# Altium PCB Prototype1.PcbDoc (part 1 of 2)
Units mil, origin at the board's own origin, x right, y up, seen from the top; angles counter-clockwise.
Board outline 2500.51 x 3790.51 mil, 6 copper layers (Signal 1, DGND, +3.3, AGND, +5/+1.2, Signal 4); 76 components, 99 nets, 527 pads, 166 vias.
Unrouted connection lines stored in the file: 15.
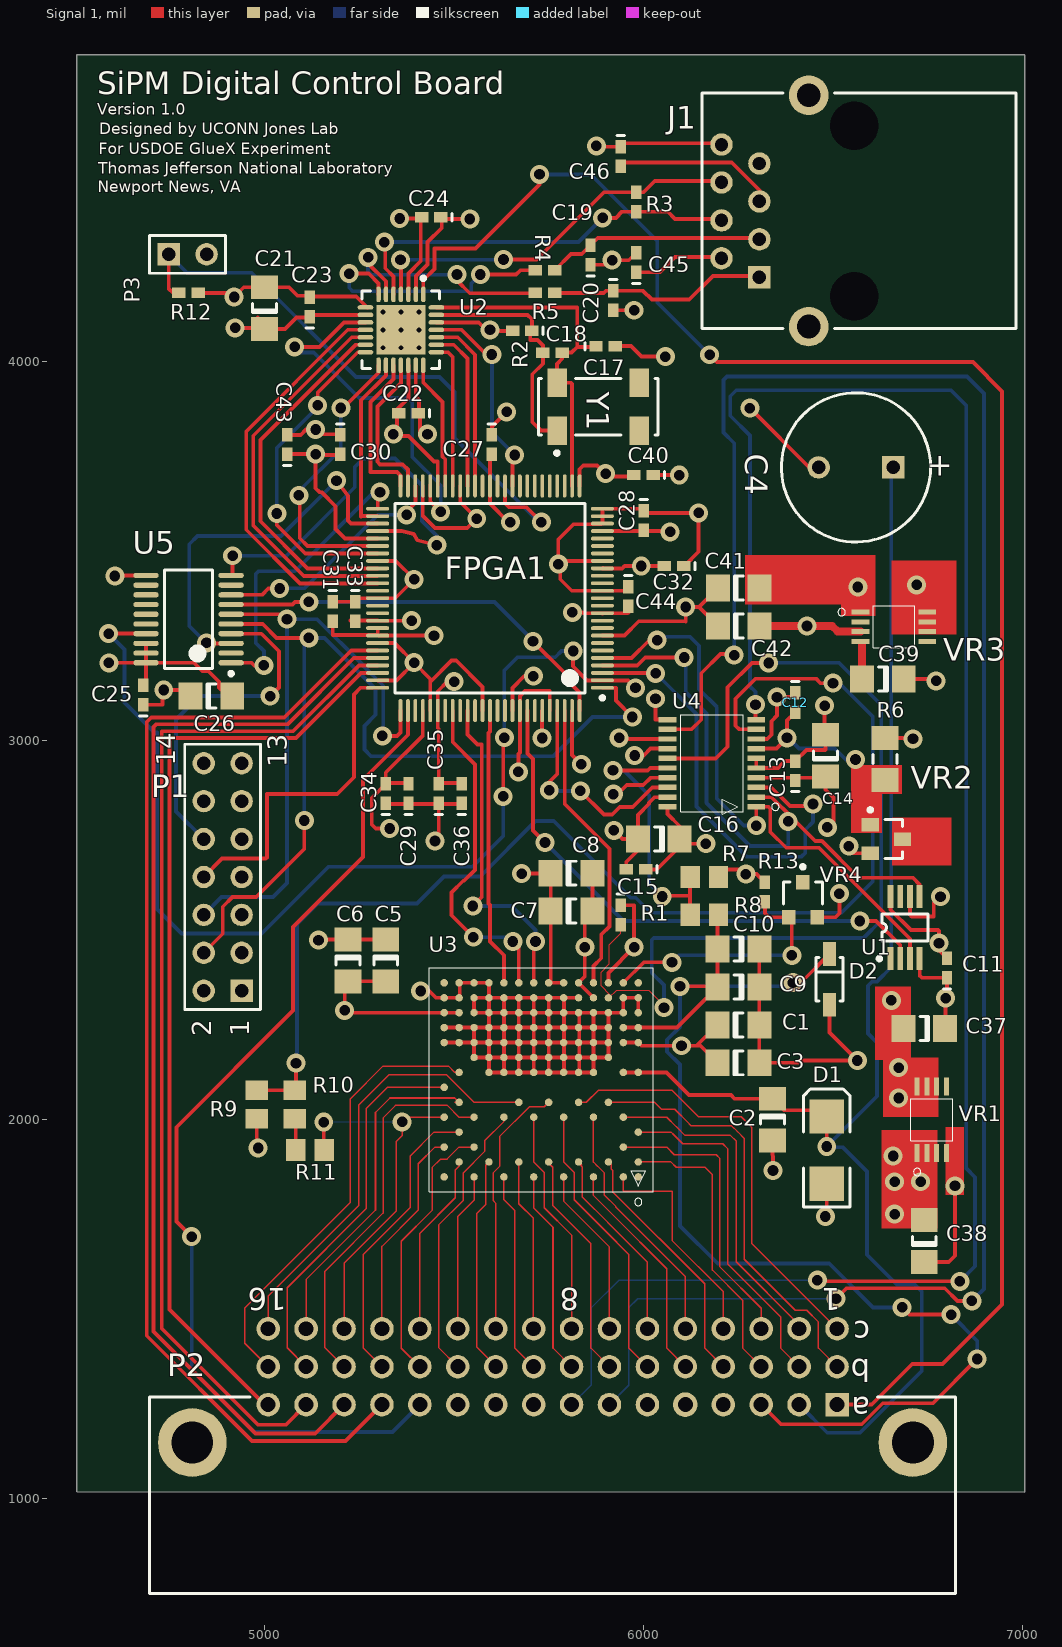
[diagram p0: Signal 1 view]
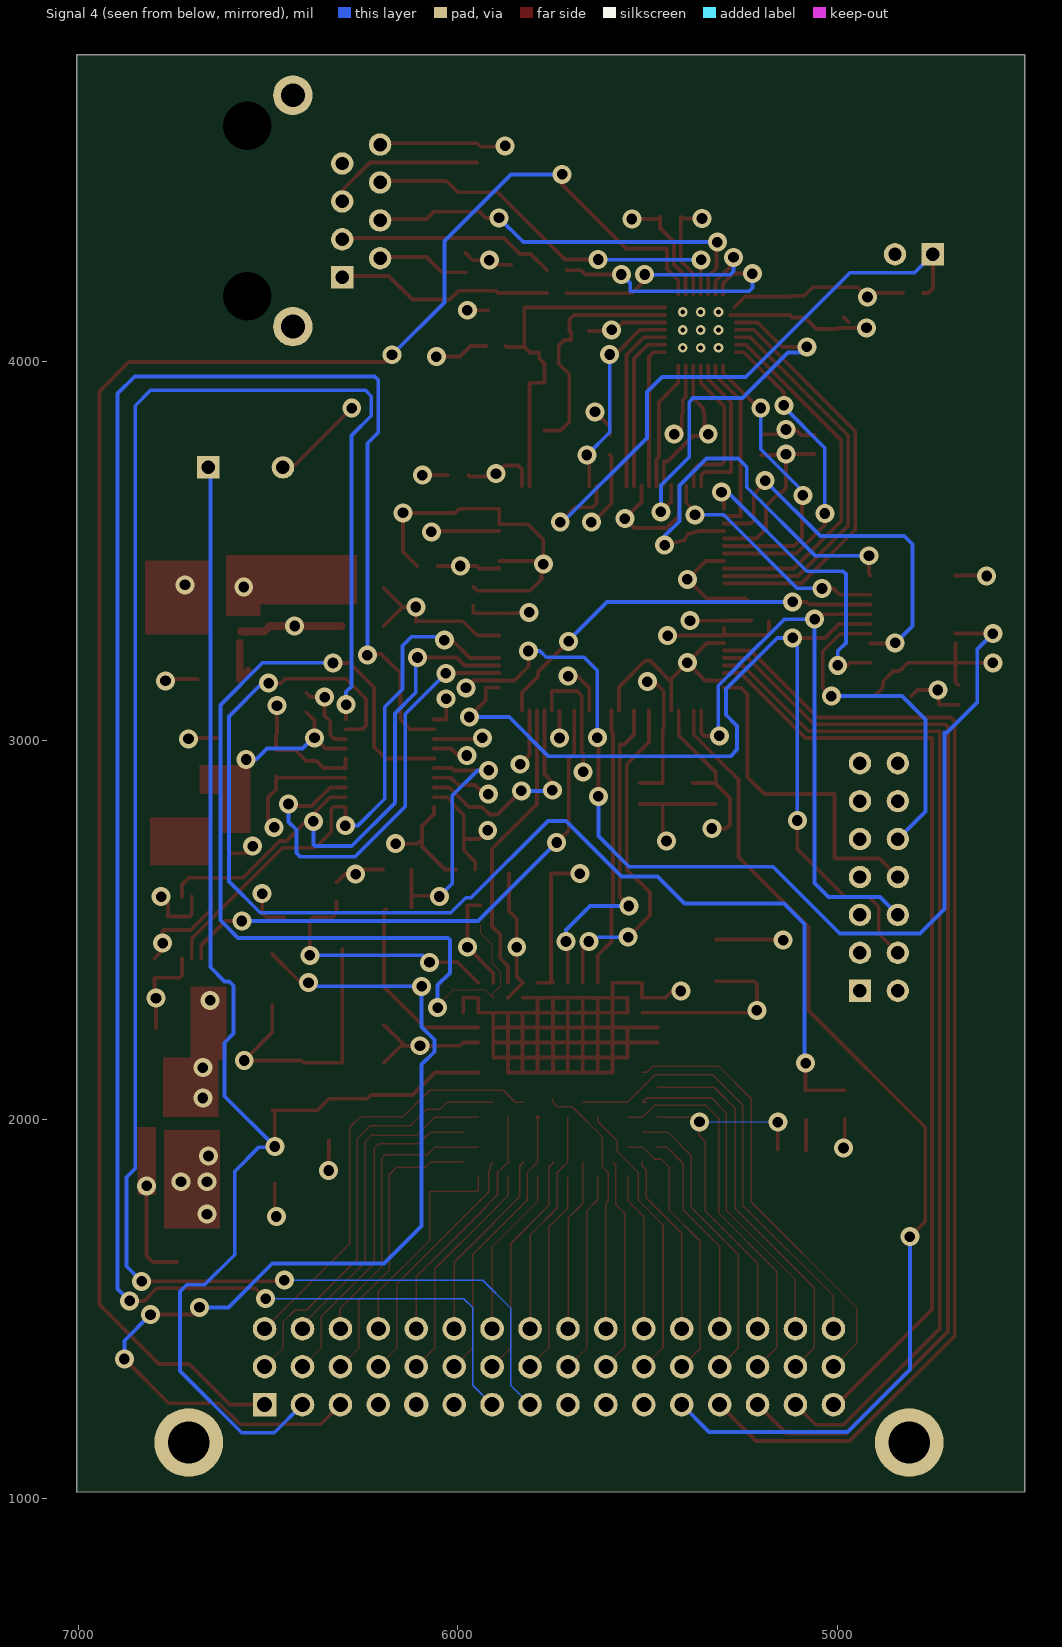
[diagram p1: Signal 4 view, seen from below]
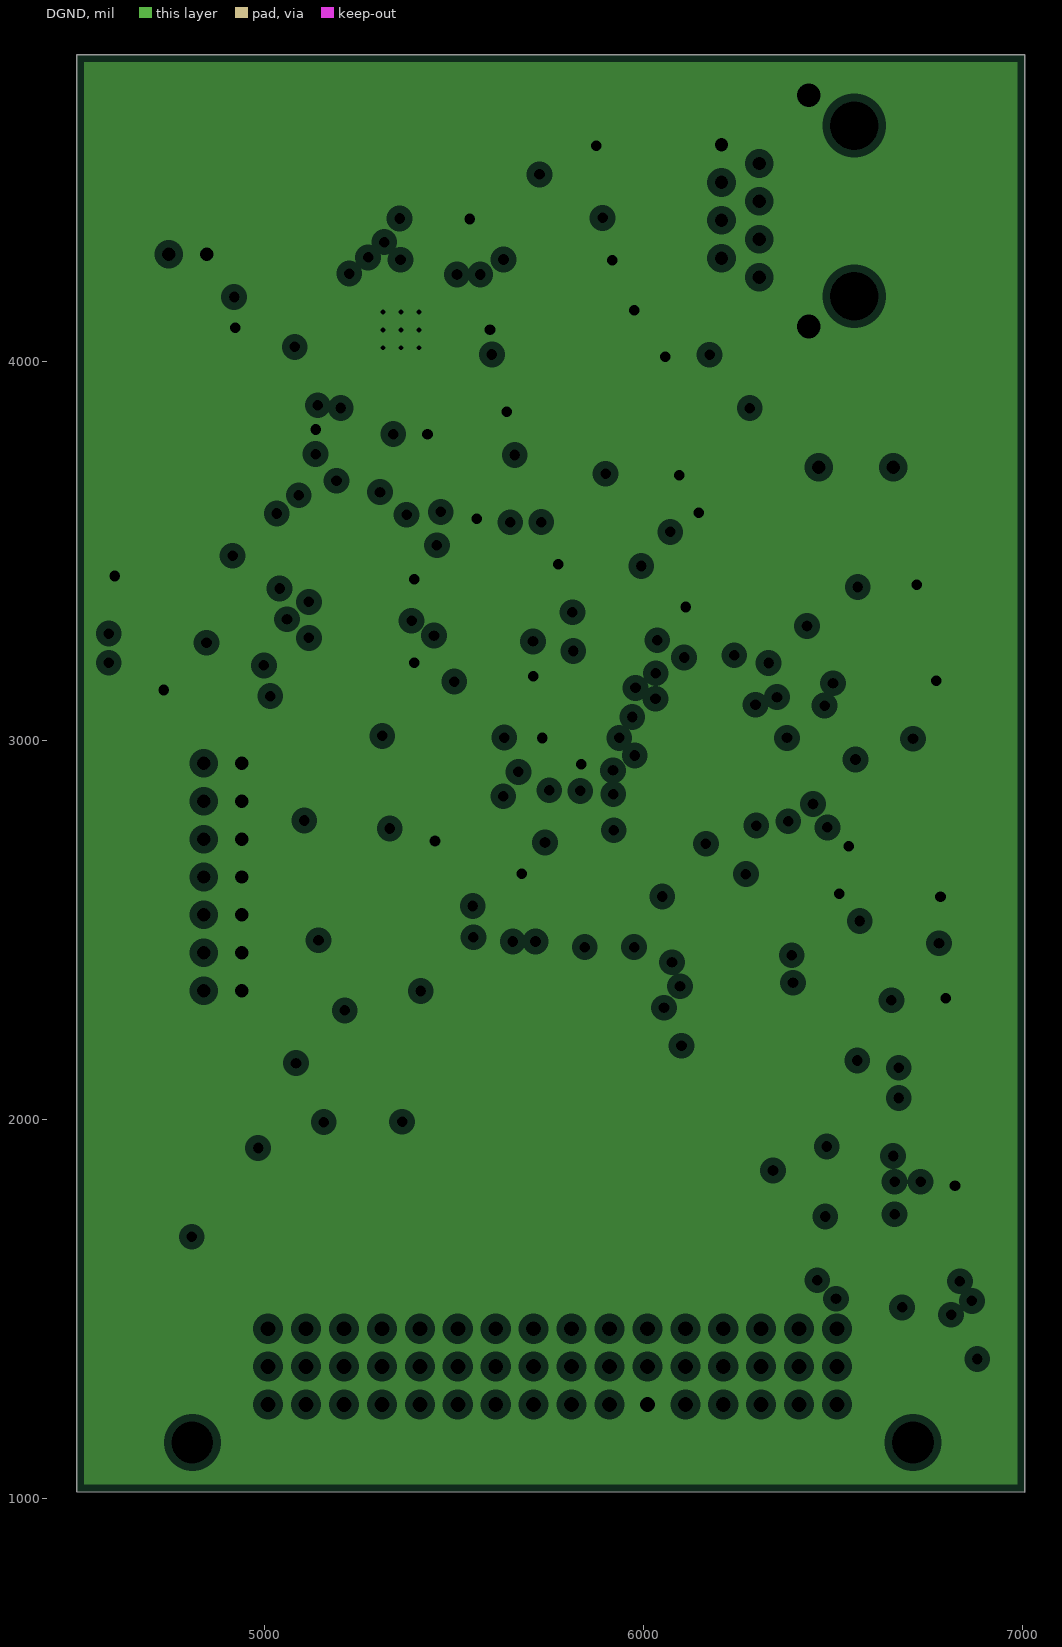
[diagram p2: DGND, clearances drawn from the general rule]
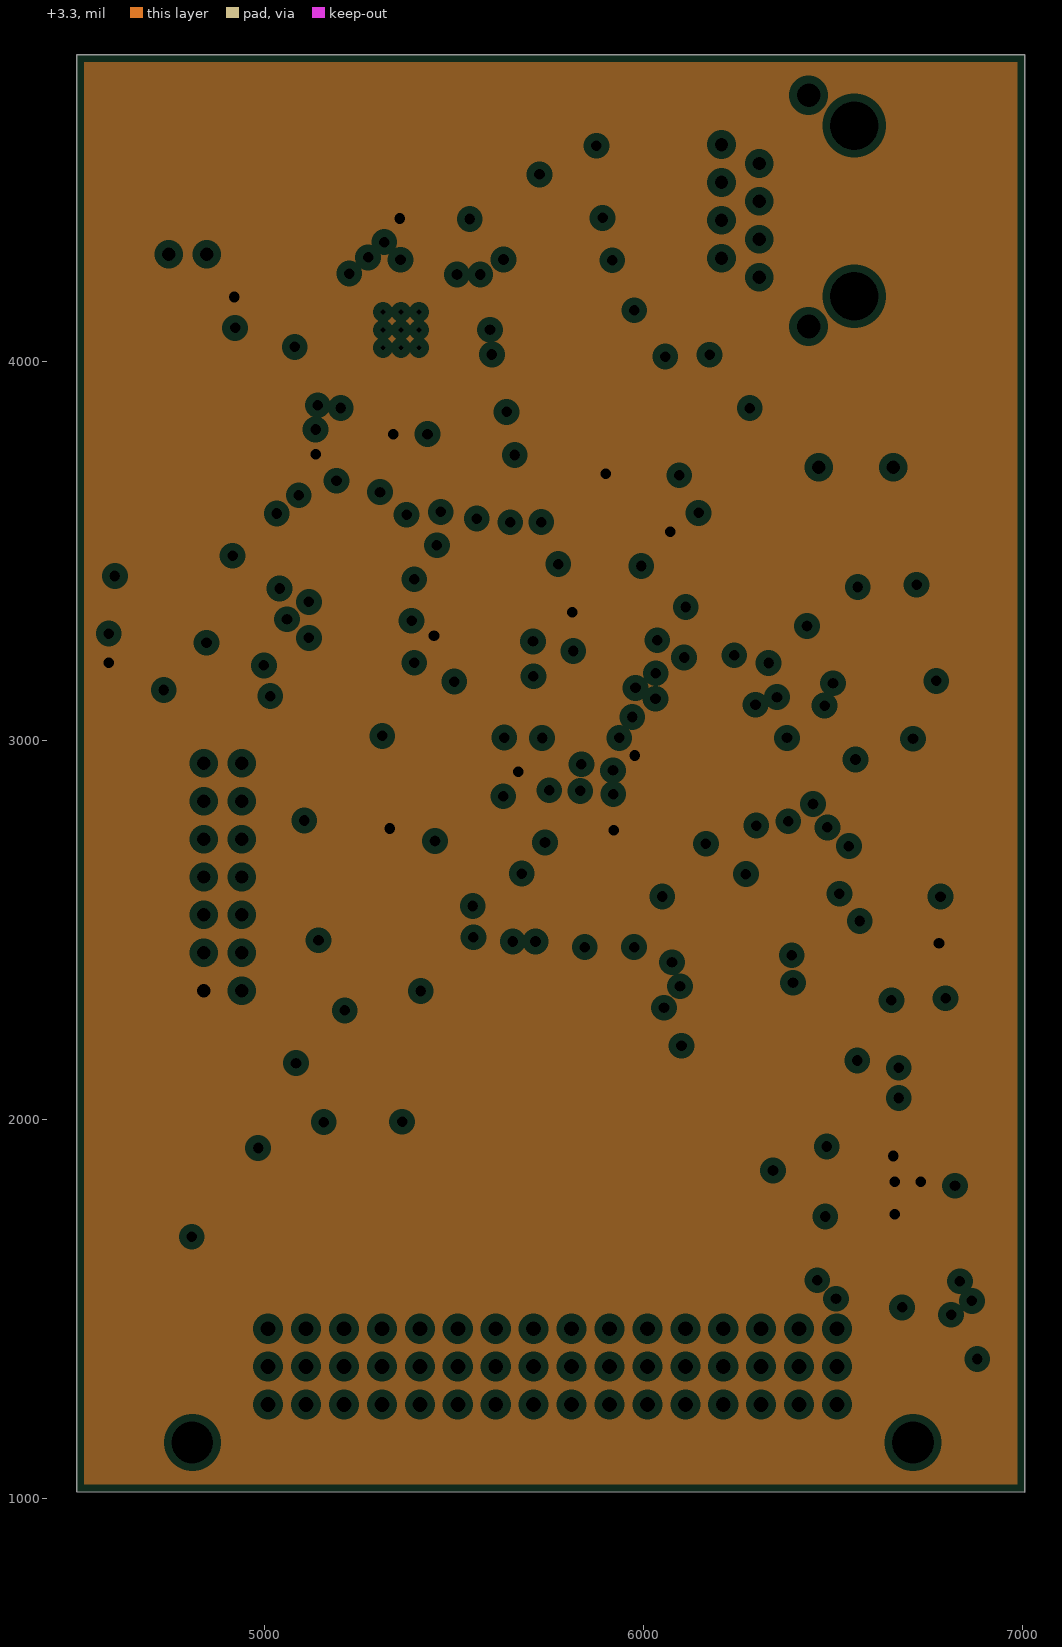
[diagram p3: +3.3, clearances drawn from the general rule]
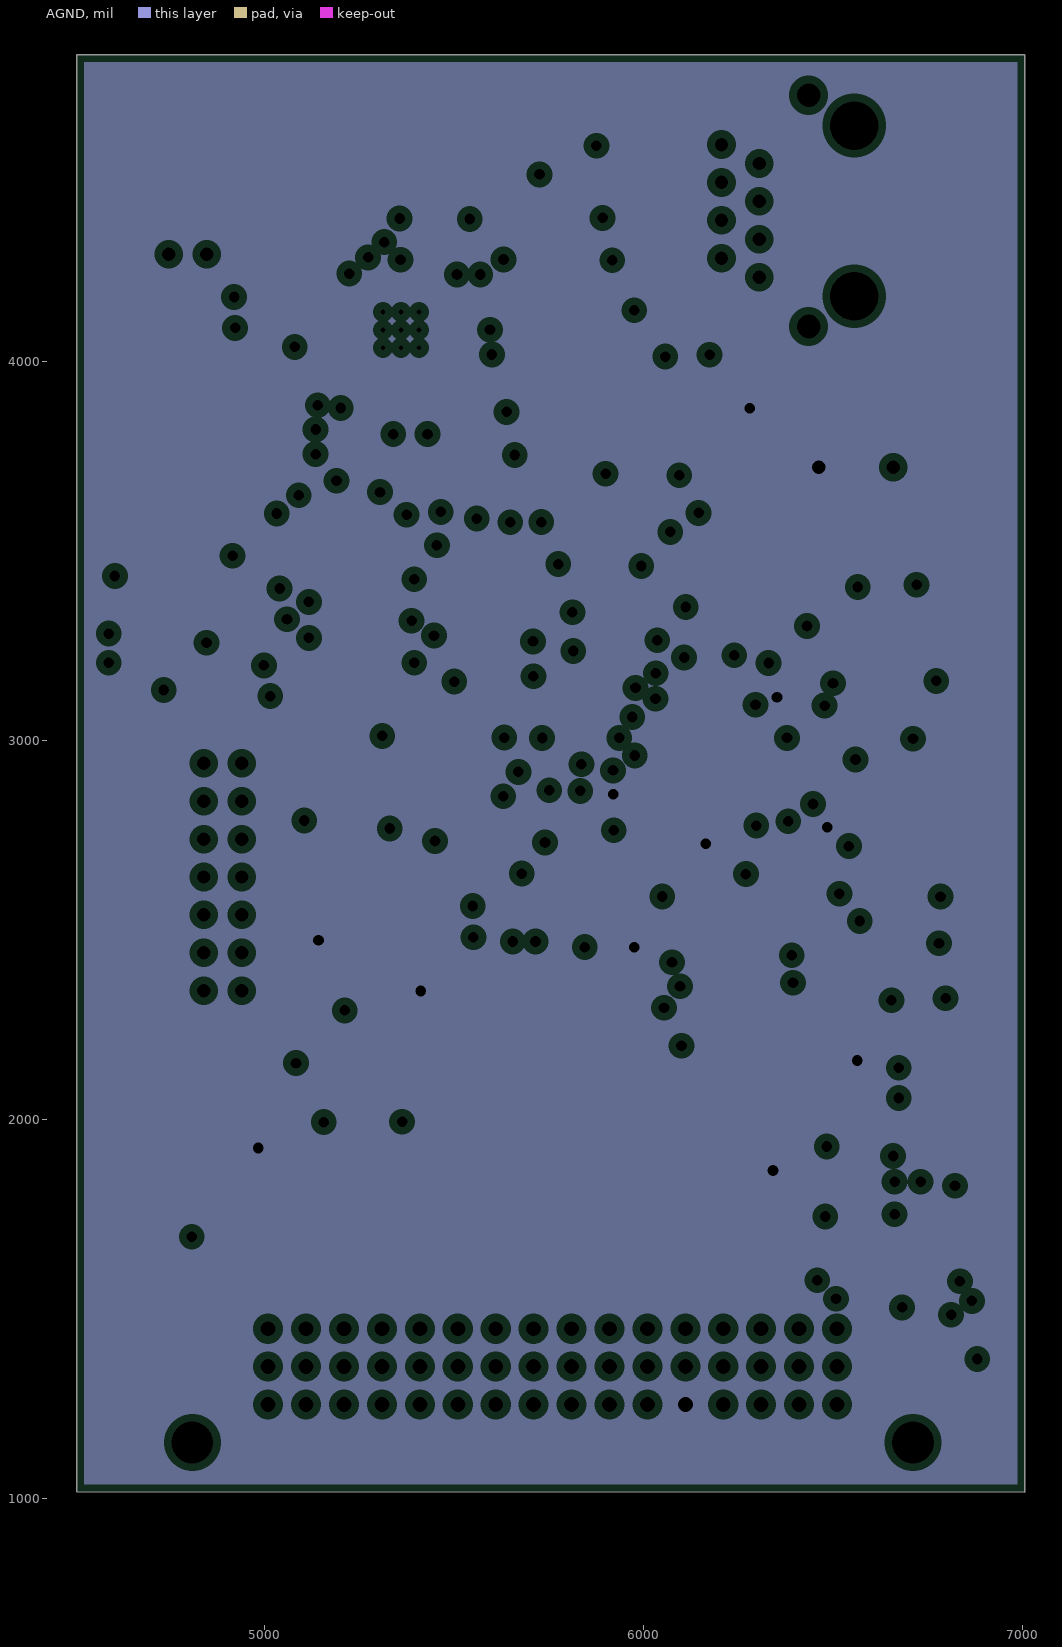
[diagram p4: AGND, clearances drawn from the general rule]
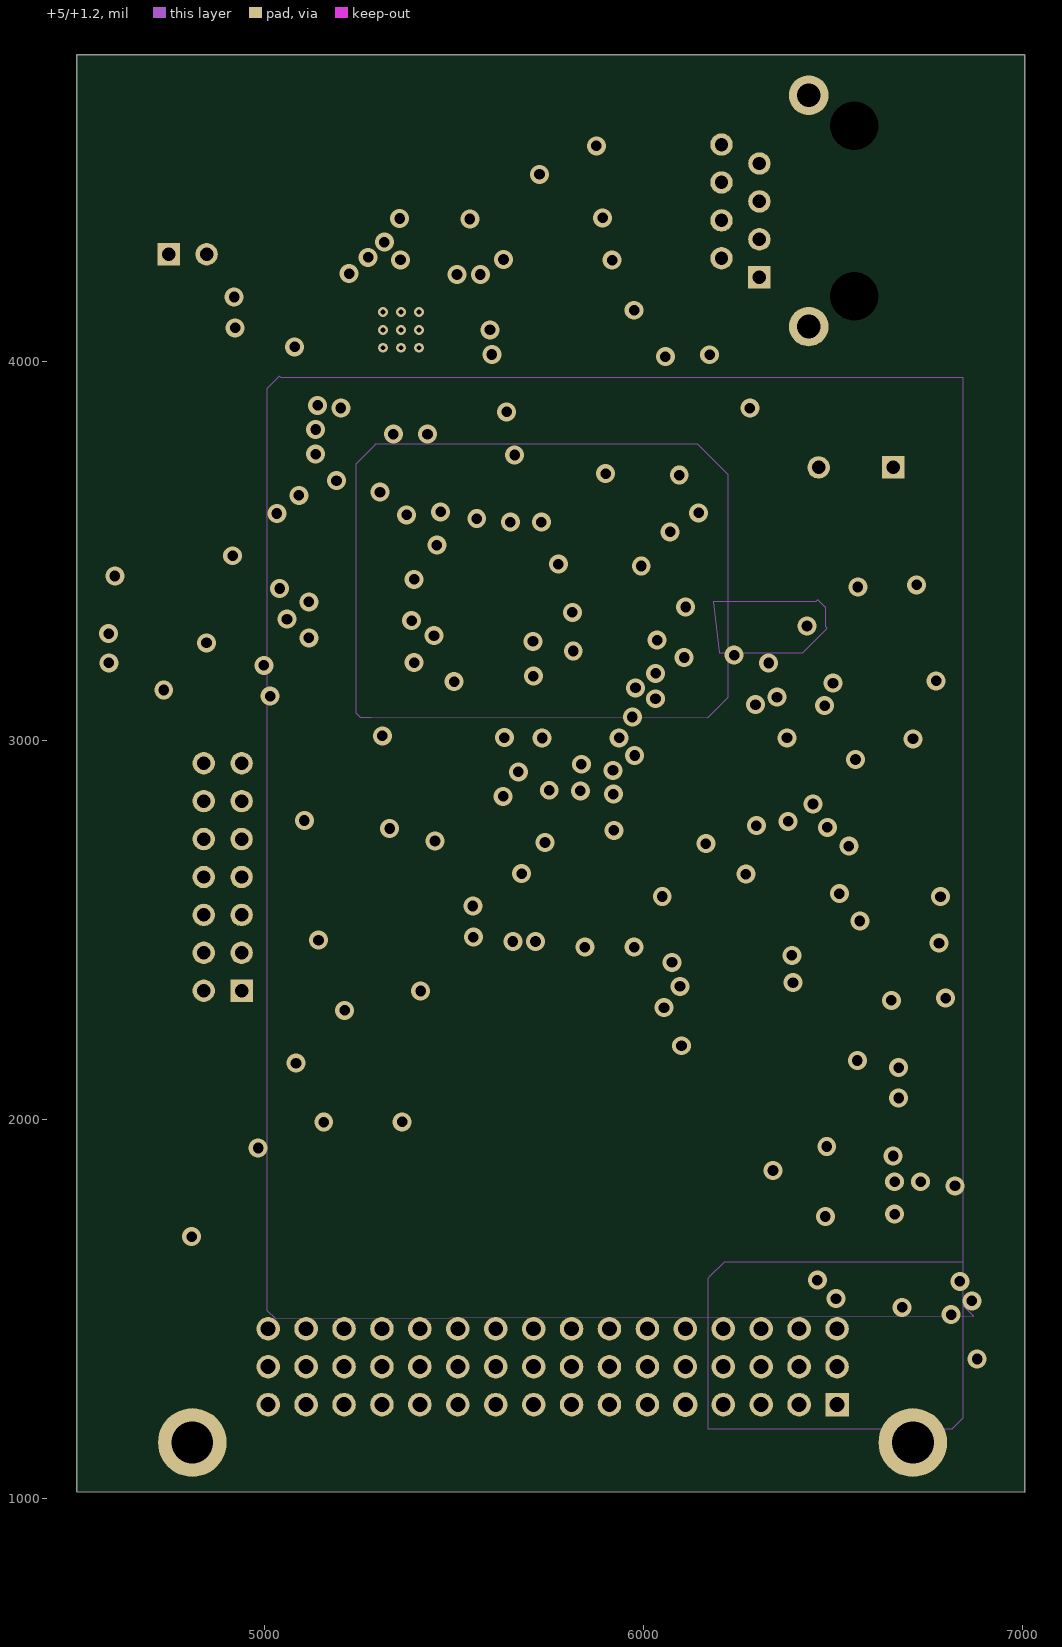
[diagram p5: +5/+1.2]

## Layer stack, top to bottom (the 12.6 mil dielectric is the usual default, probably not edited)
Signal 1: signal copper 1.4
Dielectric: core 12.6, FR-4, Dk 4.8
DGND: plane copper 1.4, net AD5535/DGND
Dielectric: prepreg 12.6, FR-4, Dk 4.8
+3.3: plane copper 1.4, net +3.3V
Dielectric: core 12.6, FR-4, Dk 4.8
AGND: plane copper 1.4, net AD5535/AGND
Dielectric: prepreg 12.6, FR-4, Dk 4.8
+5/+1.2: signal copper 1.4
Dielectric: core 12.6, FR-4, Dk 4.8
Signal 4: signal copper 1.4

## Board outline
7005.5,1017.89 7005.5,4808.4 4504.99,4808.4 4504.99,1018.96

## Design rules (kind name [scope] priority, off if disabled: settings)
Clearance "SiPM AD5535 Clearance" [(InNetClass('SiPM Bias Voltages')) vs (InComponent('U3'))] p1: gap=15.94
Clearance "CP2201 Clearance" [(InComponent('U2'))] p2: gap=4
Clearance "SiPM Bias Clearance" [InNetClass('SiPM Bias Voltages')] p3: gap=15.75
Clearance [All] p4: gap=8
ComponentClearance [All] p1: gap=10 collisioncheckmode=3 verticalgap=10
HoleSize [All] p1: absolutevalues=TRUE maxlimit=200 minlimit=1 maxpercent=80.000 minpercent=20.000
PlaneClearance [All] p1: clearance=20
PlaneConnect [All] p1: planeconnectstyle=Relief reliefexpansion=20 reliefentries=4 reliefconductorwidth=10 reliefairgap=10
PolygonConnect [All] p1: connectstyle=Relief reliefconductorwidth=10 reliefentries=4 polygonreliefangle="90 Angle"
RoomDefinition "AD5535 Power Regulators" [InComponentClass('AD5535 Power Regulators')] p1: confinementstyle=ConfineIn formatcopy=TRUE lockcomponents=FALSE outline 4775,1345 6870,1345 6870,3997.8 4775,3997.8
RoomDefinition FPGA [InComponentClass('FPGA')] p2: confinementstyle=ConfineIn formatcopy=TRUE lockcomponents=FALSE outline 4576.58,2735 6855,2735 6855,4403.79 4576.58,4403.79
RoomDefinition "Backplane Connector" [InComponentClass('Backplane Connector')] p3: confinementstyle=ConfineIn formatcopy=TRUE lockcomponents=FALSE outline 4634.69,710.9 6981.5,710.9 6981.5,1598.6 4634.69,1598.6
RoomDefinition AD5535 [InComponentClass('AD5535')] p4: confinementstyle=ConfineIn formatcopy=TRUE lockcomponents=FALSE outline 6633.36,2854.7 5410,2854.7 5410,1450 6633.36,1450
RoomDefinition AD7314 [InComponentClass('AD7314')] p5: confinementstyle=ConfineIn formatcopy=TRUE lockcomponents=FALSE outline 6594.5,2316.5 6965.5,2316.5 6965.5,2706.5 6594.5,2706.5
RoomDefinition AD7928 [InComponentClass('AD7928')] p6: confinementstyle=ConfineIn formatcopy=TRUE lockcomponents=FALSE outline 4825.67,1775.82 7046.7,1775.82 7046.7,3244.9 4825.67,3244.9
RoomDefinition CP2201 [InComponentClass('CP2201')] p7: confinementstyle=ConfineIn formatcopy=TRUE lockcomponents=FALSE outline 4520.07,3240 6992.4,3240 6992.4,4977.8 4520.07,4977.8
RoomDefinition EEPROM [InComponentClass('EEPROM')] p8: confinementstyle=ConfineIn formatcopy=TRUE lockcomponents=FALSE outline 4520.07,2135.7 5121.9,2135.7 5121.9,4105 4520.07,4105
RoomDefinition "Power and Voltage Regulators" [InComponentClass('Power and Voltage Regulators')] p9: confinementstyle=ConfineIn formatcopy=TRUE lockcomponents=FALSE outline 6519.3,1420.7 6979.7,1420.7 6979.7,2357.2 6519.3,2357.2
RoutingVias [All] p1: holewidth=28 width=50 viastyle="Through Hole" minholewidth=28 minwidth=50 maxholewidth=28 maxwidth=50
SolderMaskExpansion [All] p1: expansion=4
TestPointUsage [All] p1: valid=0 allowmultiple=FALSE
Testpoint [All] p1: side=15 testpointundercomponent=TRUE minsize=40 maxsize=100 preferedsize=60 minholesize=0 maxholesize=40 preferedholesize=32 testpointgrid=1 style=1023 order=0123456789
Width "SiPM Bias Trace Width" [InNetClass('SiPM Bias Voltages')] p1: maxlimit=10 minlimit=4 preferedwidth=4
Width [All] p2: maxlimit=20 minlimit=2 preferedwidth=10 midlayer1_minwidth=10 midlayer1_maxwidth=10 bottomlayer_maxwidth=10 minimp=50.000000 maximp=50.000000 favimp=50.000000
15 further rules are at their usual default settings.

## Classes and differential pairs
component class "Power and Voltage Regulators": C37 C38 VR1
component class FPGA: C27 C28 C29 C30 C31 C32 C33 C34 C35 C36 C39 C40 C41 C42 C43 C44 FPGA1 P3 R12 VR3
component class EEPROM: C25 C26 P1 U5
component class CP2201: C17 C18 C19 C20 C21 C22 C23 C24 C45 C46 J1 R2 R3 R4 R5 U2 Y1
component class "Backplane Connector": P2
component class AD7928: C12 C13 C14 C15 C16 R6 R7 R8 R9 R10 R11 U4 VR2
component class AD7314: C11 U1
component class AD5535: R1 R13 U3 VR4
component class "AD5535 Power Regulators": C1 C2 C3 C4 C5 C6 C7 C8 C9 C10 D1 D2

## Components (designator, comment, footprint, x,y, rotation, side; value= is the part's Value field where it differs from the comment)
C1 "Kemet C1206C104K5RACTU" C1206 6250,2250 r0 top
C2 "Kemet C1206C104KARACTU" C1206 6340,2000 r270 top
C3 "Kemet C1206C106K9PACTU" C1206 6250,2150 r0 top
C4 "Panasonic ECA-2EM100" CAPPR5-10x16 6560,3720 r180 top
C5 "Kemet C1206C106K9PACTU" C1206 5320,2420 r270 top
C6 "Kemet C1206C104K5RACTU" C1206 5220,2420 r270 top
C7 "Kemet C1206C106K9PACTU" C1206 5810,2550 r0 top
C8 "Kemet C1206C104K5RACTU" C1206 5810,2650 r0 top
C9 "Kemet C1206C106K9PACTU" C1206 6250,2350 r180 top
C10 "Kemet C1206C104K5RACTU" C1206 6250,2450 r180 top
C11 "Panasonic ECJ-0EF1C104Z" 0402 6800,2400 r90 top
C12 "Panasonic ECJ-0EF1C104Z" 0402 6400,3100 r270 top
C13 "Panasonic ECJ-0EF1C104Z" 0402 6400,2920 r90 top
C14 "Kemet C1206C106K9PACTU" C1206 6480,2960 r90 top
C15 "Panasonic ECJ-0EF1C104Z" 0402 5980,2660 r180 top
C16 "Kemet C1206C106K9PACTU" C1206 6040,2740 r180 top
C17 "Kemet C0402C220J5GACTU" 0402 5900,4040 r0 top
C18 "Kemet C0402C220J5GACTU" 0402 5680,4080 r180 top
C19 "Kemet C0402C102K5RACTU" 0402 5860,4280 r90 top
C20 "Kemet C0402C102K5RACTU" 0402 5920,4160 r270 top
C21 "Kemet C1206C106K9PACTU" C1206 5000,4140 r90 top
C22 "Panasonic ECJ-0EF1C104Z" 0402 5380,3862.8 r180 top
C23 "Panasonic ECJ-0EF1C104Z" 0402 5120,4142.8 r90 top
C24 "Panasonic ECJ-0EF1C104Z" 0402 5440,4380 r180 top
C25 "Panasonic ECJ-0EF1C104Z" 0402 4680,3120 r90 top
C26 "Kemet C1206C106K9PACTU" C1206 4860,3117.04 r0 top
C27 "Kemet C0402C101J3GACTU" 0402 5600,3780 r270 top
C28 "Kemet C0402C101J3GACTU" 0402 6000,3580 r270 top
C29 "Panasonic ECJ-0EF1C104Z" 0402 5380,2860 r90 top
C30 "Kemet C0402C101J3GACTU" 0402 5200,3780 r270 top
C31 "Kemet C0402C101J3GACTU" 0402 5180,3340 r270 top
C32 "Kemet C0402C101J3GACTU" 0402 6080,3460 r180 top
C33 "Kemet C0402C101J3GACTU" 0402 5240,3340 r270 top
C34 "Kemet C0402C101J3GACTU" 0402 5320,2860 r90 top
C35 "Panasonic ECJ-0EF1C104Z" 0402 5460,2860 r90 top
C36 "Kemet C0402C101J3GACTU" 0402 5520,2860 r90 top
C37 "Kemet C1206C105K3RACTU" C1206 6740,2240 r180 top
C38 "Kemet C1206C105K3RACTU" C1206 6740,1680 r90 top
C39 "Yageo RC0402FR-07100RL" C1206 6630.9,3161.8 r180 top
C40 "Kemet C0402C101J3GACTU" 0402 6000,3700 r180 top
C41 "Kemet C1206C225K4RACTU" C1206 6250.9,3401.8 r0 top
C42 "Kemet C1206C225K4RACTU" C1206 6250.9,3301.8 r0 top
C43 "Kemet C0402C101J3GACTU" 0402 5060,3780 r90 top
C44 "Kemet C0402C101J3GACTU" 0402 5960,3380 r270 top
C45 "Panasonic ECJ-0EF1C104Z" 0402 5980,4260 r90 top
C46 "Panasonic ECJ-0EF1C104Z" 0402 5940,4540 r270 top
D1 "Diodes, Inc. RS1GB-13-F" SMB 6483,1919.7 r90 top
D2 "Micro Commercial Co. SD103BW-TP" 425 6490,2370 r270 top
FPGA1 "Xilinx XC3S50AVQ100" VQ100_L 5595,3375 r180 top
J1 "Pulse  J0011D21NL" 43249-8925 6982.5,4396.4 r90 top
P1 "3M 2514-6002UB" HDR2X7 4940,2340 r90 top
P2 "Tyco Electronics Amp 5650916-5" EURO2.54-2H48 5760,1040 r180 top
P3 "Molex/Waldom Electronics Corp 22-10-2021" HDR1X2 4747.57,4281.99 r0 top
R1 "Rohm MCR01MZPF2703" 0402 5940,2540 r270 top
R2 "Vishay/Dale CRCW040210M0FKED" 1005[0402] 5760,4022.8 r180 top
R3 "Yageo CC1206KRX7R9BB103" 1005[0402] 5980,4420 r90 top
R4 "Vishay/Dale CRCW04028R06FNED" 1005[0402] 5740,4240 r0 top
R5 "Vishay/Dale CRCW04028R06FNED" 1005[0402] 5740,4180 r0 top
R6 "Rohm MCR18EZHF2702" 3216[1206] 6636.7,2951.1 r270 top
R7 "Rohm MCR10EZHF3322" 2012[0805] 6160,2640 r0 top
R8 "Rohm MCR10EZHF1003" 2012[0805] 6160,2540 r180 top
R9 "Rohm MCR10EZHF1022" 2012[0805] 4980,2040 r270 top
R10 "Panasonic ERJ-6ENF2003V" 2012[0805] 5080,2040 r270 top
R11 "Panasonic ERJ-6ENF2003V" 2012[0805] 5120,1920 r0 top
R12 "Panasonic ERJ-2RKF1003X" 1005[0402] 4800,4180 r180 top
R13 "Panasonic ERJ-2RKF1003X" 1005[0402] 6320,2600 r270 top
U1 "Analog Devices AD7314" RM-8#1 6689.5,2506.5 r0 top
U2 "Silicon Laboratories CP2201" QFN50P500X500-28V1N 5360,4082.8 r270 top
U3 "Analog Devices AD5535" BC-124 5730,2105 r180 top
U4 "Analog Devices AD7928" RU-20 6180,2940 r90 top
U5 "Xilinx XCF01SVO20C" VO20_N 4800,3320 r180 top
VR1 "Analog Devices ADP3335ARMZ-3.3-RL" RM-8#2 6760,2000 r0 top
VR2 "National Semiconductor LM4040DIM3-2.5/NOPB" M03B 6640,2740 r270 top
VR3 "Analog Devices ADP1715ARMZ-1.2-R7" RM-8#2 6660,3300 r270 top
VR4 "Zetex, Inc. ZRC330F01TA" SOT23 6420,2580 r0 top
Y1 "Epson Toyocom Corporation MA-306 20.0000M-C0:ROHS" DSO-N4 5880,3880 r0 top

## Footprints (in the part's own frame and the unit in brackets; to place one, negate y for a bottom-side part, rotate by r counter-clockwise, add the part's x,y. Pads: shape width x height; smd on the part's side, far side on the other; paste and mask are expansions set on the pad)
0402 [mm] "Chip Capacitor; Body 1.0 x 0.5 mm (LxW typ)"
  rect 0.9x0.7 smd: 1(-0.65,0) 2(0.65,0)
  silkscreen extent -1.4,-0.25 -1.4,0.25
425 [mm] "SOD-123; 2 Leads; Body 2.7 x 1.6 mm, (LxW)"
  rect 1.6x0.85 smd: 1(-1.7,0) 2(1.7,0)
  silkscreen extent -1.45,-0.9 1.45,0.9
1005[0402] [mm] "Chip Resistor; Body 1.1 x 0.5 mm (LxW typ)"
  rect 0.9x0.7 smd: 1(-0.65,0) 2(0.65,0)
2012[0805] [mm] "Chip Resistor; Body 2.0 x 1.3 mm (LxW typ)"
  rect 1.3x1.5 smd: 1(-0.95,0) 2(0.95,0)
3216[1206] [mm] "Chip Resistor; Body 3.2 x 1.6 mm (LxW typ)"
  rect 1.6x1.8 smd: 1(-1.4,0) 2(1.4,0)
  silkscreen extent -0.3,-0.8 0.3,0.8
43249-8925 [mm] "Connector; PCB Jack, Thru-Hole; 1-Port, 8 Positions, 8 Loaded; Shielded without Lightpipes; Right Angle"
  rect 1.5x1.5 hole 0.9: 1(-4.445,17.2)
  round 1.5 hole 0.9: 2(-3.175,19.74) 3(-1.905,17.2) 4(-0.635,19.74) 5(0.635,17.2) 6(1.905,19.74) 7(3.175,17.2) 8(4.445,19.74)
  round 2.65 hole 1.6: MH1(-7.747,13.898) MH2(7.747,13.898)
  round 2.95 hole 3.25 unplated: MH3(-5.715,10.85) MH4(5.715,10.85)
  silkscreen extent -7.88,0 7.89,21.05
BC-124 [mil]
  round 19.7 smd: A1(-255.9,255.9) A2(-216.5,255.9) A4(-137.8,255.9) A6(-59.1,255.9) A8(19.7,255.9) A10(98.4,255.9) A12(177.2,255.9) A14(255.9,255.9) B1(-255.9,216.5) B3(-177.2,216.5) B5(-98.4,216.5) B7(-19.7,216.5) B9(59.1,216.5) B11(137.8,216.5) B13(216.5,216.5) C2(-216.5,177.2) C12(177.2,177.2) C14(255.9,177.2) D1(-255.9,137.8) D13(216.5,137.8) E2(-216.5,98.4) E4(-137.8,98.4) E6(-59.1,98.4) E8(19.7,98.4) E10(98.4,98.4) E12(177.2,98.4) E14(255.9,98.4) F3(-177.2,59.1) F5(-98.4,59.1) F7(-19.7,59.1) F9(59.1,59.1) F13(216.5,59.1) G14(255.9,19.7) H1(-255.9,-19.7) H2(-216.5,-19.7) H4(-137.8,-19.7) H5(-98.4,-19.7) H6(-59.1,-19.7) H7(-19.7,-19.7) H8(19.7,-19.7) H9(59.1,-19.7) H10(98.4,-19.7) H11(137.8,-19.7) H13(216.5,-19.7) J3(-177.2,-59.1) J4(-137.8,-59.1) J5(-98.4,-59.1) J6(-59.1,-59.1) J7(-19.7,-59.1) J8(19.7,-59.1) J9(59.1,-59.1) J10(98.4,-59.1) J11(137.8,-59.1) J12(177.2,-59.1) K1(-255.9,-98.4) K2(-216.5,-98.4) K3(-177.2,-98.4) K4(-137.8,-98.4) K5(-98.4,-98.4) K6(-59.1,-98.4) K7(-19.7,-98.4) K8(19.7,-98.4) K9(59.1,-98.4) K10(98.4,-98.4) K11(137.8,-98.4) K12(177.2,-98.4) K13(216.5,-98.4) K14(255.9,-98.4) L1(-255.9,-137.8) L2(-216.5,-137.8) L3(-177.2,-137.8) L4(-137.8,-137.8) L5(-98.4,-137.8) L6(-59.1,-137.8) L7(-19.7,-137.8) L8(19.7,-137.8) L9(59.1,-137.8) L10(98.4,-137.8) L11(137.8,-137.8) L12(177.2,-137.8) L13(216.5,-137.8) L14(255.9,-137.8) M1(-255.9,-177.2) M2(-216.5,-177.2) M3(-177.2,-177.2) M4(-137.8,-177.2) M5(-98.4,-177.2) M6(-59.1,-177.2) M7(-19.7,-177.2) M8(19.7,-177.2) M9(59.1,-177.2) M10(98.4,-177.2) M11(137.8,-177.2) M12(177.2,-177.2) M13(216.5,-177.2) M14(255.9,-177.2) N1(-255.9,-216.5) N2(-216.5,-216.5) N3(-177.2,-216.5) N4(-137.8,-216.5) N5(-98.4,-216.5) N6(-59.1,-216.5) N7(-19.7,-216.5) N8(19.7,-216.5) N9(59.1,-216.5) N10(98.4,-216.5) N11(137.8,-216.5) N12(177.2,-216.5) N13(216.5,-216.5) N14(255.9,-216.5) P1(-255.9,-255.9) P2(-216.5,-255.9) P3(-177.2,-255.9) P4(-137.8,-255.9) P5(-98.4,-255.9) P6(-59.1,-255.9) P7(-19.7,-255.9) P8(19.7,-255.9) P9(59.1,-255.9) P10(98.4,-255.9) P11(137.8,-255.9) P12(177.2,-255.9) P13(216.5,-255.9) P14(255.9,-255.9)
  silkscreen extent -295,-295 295,332
C1206 [mm] "Chip Capacitor; Body 3.2 x 1.6 mm (LxW typ)"
  rect 1.6x1.8 smd: 1(-1.4,0) 2(1.4,0)
  silkscreen extent -0.3,-0.8 0.3,0.8
CAPPR5-10x16 [mm] "Capacitor, Electrolytic, Radial; Body 10 x 16 mm (Dia.xH typ); Pin Spacing 5 mm (typ)"
  rect 1.5x1.5 hole 0.9: 1(-2.5,0)
  round 1.5 hole 0.9: 2(2.5,0)
  silkscreen extent -5,-5 5,5
DSO-N4 [mm] "Crystal, SM; 4 Leads; Body 8 x 3.8 x 2.5 mm (LxWxH)"
  rect 1.3x1.9 smd: 1(-2.75,-1.6) 2(2.75,-1.6) 3(2.75,1.6) 4(-2.75,1.6)
  silkscreen extent -4,-3.22 4,1.9
EURO2.54-2H48 [mm] "Connector; DIN 41612, Type 2C, Thru-Hole; Rows a+b+c, 48 Position; Right Angle"
  round 4.6 hole 2.8: 17(-24.13,-2.76) 18(24.13,-2.76)
  rect 1.575x1.575 hole 1: A1(-19.05,-5.3)
  round 1.575 hole 1: A2(-16.51,-5.3) A3(-13.97,-5.3) A4(-11.43,-5.3) A6(-6.35,-5.3) A7(-3.81,-5.3) A8(-1.27,-5.3) A9(1.27,-5.3) A10(3.81,-5.3) A11(6.35,-5.3) A12(8.89,-5.3) A13(11.43,-5.3) A14(13.97,-5.3) A15(16.51,-5.3) A16(19.05,-5.3) B1(-19.05,-7.84) B2(-16.51,-7.84) B3(-13.97,-7.84) B4(-11.43,-7.84) B5(-8.89,-7.84) B6(-6.35,-7.84) B7(-3.81,-7.84) B8(-1.27,-7.84) B9(1.27,-7.84) B10(3.81,-7.84) B11(6.35,-7.84) B12(8.89,-7.84) B13(11.43,-7.84) B14(13.97,-7.84) B15(16.51,-7.84) B16(19.05,-7.84) C1(-19.05,-10.38) C2(-16.51,-10.38) C3(-13.97,-10.38) C4(-11.43,-10.38) C5(-8.89,-10.38) C6(-6.35,-10.38) C7(-3.81,-10.38) C8(-1.27,-10.38) C9(1.27,-10.38) C10(3.81,-10.38) C11(6.35,-10.38) C12(8.89,-10.38) C13(11.43,-10.38) C14(13.97,-10.38) C15(16.51,-10.38) C16(19.05,-10.38)
  round 1.65 hole 1: A5(-8.89,-5.3)
  silkscreen extent -27,-5.8 27,7.34
HDR1X2 [mm] "Connector; Header; 2 Position"
  rect 1.5x1.5 hole 0.9: 1(0,0)
  round 1.5 hole 0.9: 2(2.54,0)
  silkscreen extent -1.27,-1.27 3.81,1.27
HDR2X7 [mm] "Connector; Header; 7x2 Position"
  rect 1.5x1.5 hole 0.9: 1(0,0)
  round 1.5 hole 0.9: 2(0,2.54) 3(2.54,0) 4(2.54,2.54) 5(5.08,0) 6(5.08,2.54) 7(7.62,0) 8(7.62,2.54) 9(10.16,0) 10(10.16,2.54) 11(12.7,0) 12(12.7,2.54) 13(15.24,0) 14(15.24,2.54)
  silkscreen extent -1.27,-1.27 16.51,3.81
M03B [mm] "SOT-23; 3 Leads; Body 3.0 x 2.5 mm, inc. leads (LxW max)"
  rect 0.9x1.15 smd: 1(-0.95,-1.075) 2(0.95,-1.075) 3(0,1.075)
  silkscreen extent -2.07,-1.2 1.3,1.07
QFN50P500X500-28V1N [mm] "QFN, 28-Leads, Body 5x5mm, Pitch 0.5mm, IPC Medium Density"
  oval 1.05x0.3 smd: 1(-2.375,1.5) 2(-2.375,1) 3(-2.375,0.5) 4(-2.375,0) 5(-2.375,-0.5) 6(-2.375,-1) 7(-2.375,-1.5) 15(2.375,-1.5) 16(2.375,-1) 17(2.375,-0.5) 18(2.375,0) 19(2.375,0.5) 20(2.375,1) 21(2.375,1.5)
  oval 0.3x1.05 smd: 8(-1.5,-2.375) 9(-1,-2.375) 10(-0.5,-2.375) 11(0,-2.375) 12(0.5,-2.375) 13(1,-2.375) 14(1.5,-2.375) 22(1.5,2.375) 23(1,2.375) 24(0.5,2.375) 25(0,2.375) 26(-0.5,2.375) 27(-1,2.375) 28(-1.5,2.375)
  rect 3.3x3.3 smd: 29(0,0)
  silkscreen extent -3.57,-2.6 2.6,2.6, body extent -2.58,-2.58 2.58,2.58, height 1
RM-8#1 [mm] "Shrink Small Outline, MSOP; 8 Leads; Body Width 3 mm; Pitch 0.65 mm"
  rect 0.4x1.55 smd: 1(-0.975,-2.075) 2(-0.325,-2.075) 3(0.325,-2.075) 4(0.975,-2.075) 5(0.975,2.075) 6(0.325,2.075) 7(-0.325,2.075) 8(-0.975,2.075)
  silkscreen extent -1.85,-2.2 1.55,0.9
RM-8#2 [mm]
  rect 0.34x1.191 smd: 1(-0.98,-2.23) 2(-0.32,-2.23) 3(0.32,-2.23) 4(0.98,-2.23) 5(0.98,2.23) 6(0.32,2.23) 7(-0.32,2.23) 8(-0.98,2.23)
  silkscreen extent -1.4,-3.75 1.4,1.4
RU-20 [mil]
  rect 14.2x46.9 smd: 1(-115,-116.9) 2(-89.8,-116.9) 3(-63.8,-116.9) 4(-38.6,-116.9) 5(-12.6,-116.9) 6(12.6,-116.9) 7(38.6,-116.9) 8(63.8,-116.9) 9(89.8,-116.9) 10(115,-116.9) 11(115,116.9) 12(89.8,116.9) 13(63.8,116.9) 14(38.6,116.9) 15(12.6,116.9) 16(-12.6,116.9) 17(-38.6,116.9) 18(-63.8,116.9) 19(-89.8,116.9) 20(-115,116.9)
  silkscreen extent -135,-177 128,83
SMB [mm] "DO-214-AA/SMB; 2 C-Bend Leads; Body 5.3 x 3.6 mm, inc. leads (LxW)"
  rect 2.3x2.3 smd: 1(-2.25,0) 2(2.25,0)
  silkscreen extent -3.8,-1.55 4.1,1.55
SOT23 [mm] "SOT-23; 3 Leads; Body 3.1 x 2.5 mm, inc. leads (LxW max), Alternate Lead Configuration"
  rect 0.9x0.95 smd: 1(0,1.175) 2(0.95,-1.175) 3(-0.95,-1.175)
  silkscreen extent -1.3,-0.3 1.3,2.32
VO20_N [mm] "TSOP, 20-Leads, Body 6.5x4.4mm, Pitch 0.65mm, IPC Medium Density"
  oval 1.7x0.35 smd: 1(-2.85,2.925) 2(-2.85,2.275) 3(-2.85,1.625) 4(-2.85,0.975) 5(-2.85,0.325) 6(-2.85,-0.325) 7(-2.85,-0.975) 8(-2.85,-1.625) 9(-2.85,-2.275) 10(-2.85,-2.925) 11(2.85,-2.925) 12(2.85,-2.275) 13(2.85,-1.625) 14(2.85,-0.975) 15(2.85,-0.325) 16(2.85,0.325) 17(2.85,0.975) 18(2.85,1.625) 19(2.85,2.275) 20(2.85,2.925)
  silkscreen extent -2.98,-3.3 1.6,3.77, body extent -2.25,-3.3 2.25,3.3, height 1.2
VQ100_L [mm] "100-Pin Very Thin Quad Flat Pack (VQ100), IPC High Density"
  oval 1.55x0.25 smd: 1(-7.525,6) 2(-7.525,5.5) 3(-7.525,5) 4(-7.525,4.5) 5(-7.525,4) 6(-7.525,3.5) 7(-7.525,3) 8(-7.525,2.5) 9(-7.525,2) 10(-7.525,1.5) 11(-7.525,1) 12(-7.525,0.5) 13(-7.525,0) 14(-7.525,-0.5) 15(-7.525,-1) 16(-7.525,-1.5) 17(-7.525,-2) 18(-7.525,-2.5) 19(-7.525,-3) 20(-7.525,-3.5) 21(-7.525,-4) 22(-7.525,-4.5) 23(-7.525,-5) 24(-7.525,-5.5) 25(-7.525,-6) 51(7.525,-6) 52(7.525,-5.5) 53(7.525,-5) 54(7.525,-4.5) 55(7.525,-4) 56(7.525,-3.5) 57(7.525,-3) 58(7.525,-2.5) 59(7.525,-2) 60(7.525,-1.5) 61(7.525,-1) 62(7.525,-0.5) 63(7.525,0) 64(7.525,0.5) 65(7.525,1) 66(7.525,1.5) 67(7.525,2) 68(7.525,2.5) 69(7.525,3) 70(7.525,3.5) 71(7.525,4) 72(7.525,4.5) 73(7.525,5) 74(7.525,5.5) 75(7.525,6)
  oval 0.25x1.55 smd: 26(-6,-7.525) 27(-5.5,-7.525) 28(-5,-7.525) 29(-4.5,-7.525) 30(-4,-7.525) 31(-3.5,-7.525) 32(-3,-7.525) 33(-2.5,-7.525) 34(-2,-7.525) 35(-1.5,-7.525) 36(-1,-7.525) 37(-0.5,-7.525) 38(0,-7.525) 39(0.5,-7.525) 40(1,-7.525) 41(1.5,-7.525) 42(2,-7.525) 43(2.5,-7.525) 44(3,-7.525) 45(3.5,-7.525) 46(4,-7.525) 47(4.5,-7.525) 48(5,-7.525) 49(5.5,-7.525) 50(6,-7.525) 76(6,7.525) 77(5.5,7.525) 78(5,7.525) 79(4.5,7.525) 80(4,7.525) 81(3.5,7.525) 82(3,7.525) 83(2.5,7.525) 84(2,7.525) 85(1.5,7.525) 86(1,7.525) 87(0.5,7.525) 88(0,7.525) 89(-0.5,7.525) 90(-1,7.525) 91(-1.5,7.525) 92(-2,7.525) 93(-2.5,7.525) 94(-3,7.525) 95(-3.5,7.525) 96(-4,7.525) 97(-4.5,7.525) 98(-5,7.525) 99(-5.5,7.525) 100(-6,7.525)
  silkscreen extent -7.65,-6.35 6.35,6.8, body extent -7,-7 7,7, height 1.2

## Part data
C1 C2 C3 C4 C5 C6 C7 C8 C9 C10 C11 C12 C13 C14 C15 C16 C17 C18 C19 C20 C21 C22 C23 C24 C25 C26 C27 C28 C29 C30 C31 C32 C33 C34 C35 C36 C37 C38 C39 C40 C41 C42 C43 C44 C45 C46: library part Cap, "Capacitor"
D1: library part Diode, "Default Diode"
D2: library part "D Schottky", "Schottky Diode"
FPGA1: library part XC3S50AVQ100
J1: library part 43249-8925, "Right Angle, Low Profile, with top Panel Grounding Tabs, Shielded PCB Jack"
P1: library part "Header 7X2", "Header, 7-Pin, Dual row"
P2: library part "DIN41612 48 Connector"
P3: library part "Header 2", "Header, 2-Pin"
R1 R2 R3 R4 R5 R6 R7 R8 R9 R10 R11 R12 R13: library part Res2, "Resistor"
U1: library part AD7314
U2: library part CP2201
U3: library part AD5535
U4: library part AD7928BRU-REEL7
U5: library part XCF01SVO20C, "XCF00S Series, Platform Flash In-System Programmable Configuration 3.3V PROM, 20-Pin TSOP, 1-Megabit, Commercial Grade"
VR1: library part ADP3335
VR2 VR4: library part LM4040DIM3-2.5, "Precision Micropower Shunt Voltage Reference"
VR3: library part ADP1715
Y1: library part XTAL, "Crystal Oscillator"

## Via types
v1: diameter 50, hole 28, Signal 1 to Signal 4, 157 vias
v2: diameter 25.98, hole 12.99, Signal 1 to Signal 4, tented top, 9 vias

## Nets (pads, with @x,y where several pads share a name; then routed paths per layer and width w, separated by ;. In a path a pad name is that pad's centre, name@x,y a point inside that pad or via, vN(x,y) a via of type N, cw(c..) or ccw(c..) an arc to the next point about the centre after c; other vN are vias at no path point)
+1.2V: C27.2 C32.2 C33.2 C35.2 C36.2 C42.2 FPGA1.17 FPGA1.38 FPGA1.66 FPGA1.81 U4.11 VR3.3 | length 1826.5
  Signal 1 w10: FPGA1.66@5298.88,3315.8 v1(5388.2,3315.8) ; v1(5500.5,3155.3) 5482.9,3155.3 5457.3,3129.7 ; C27.2@5600,3754.41 5600,3752.44 5595,3747.44 FPGA1.38@5595,3671.26 5595,3624.7 5644.1,3575.6 v1(5648.5,3575.6) ; FPGA1.17@5892.64,3455.12 FPGA1.17@5891.26,3453.74 5943.74,3453.74 5950,3460 C32.2@6052.44,3460 ; v1(5993.8,3460) C32.2@6052.44,3460 ; v1(6031.2,3110) 6031.2,3054.4 6031.8,3055 U4.11@6063.1,3055 ; C32.2@6054.41,3460 C32.2@6052.44,3460 ; C33.2@5227,3315.94 C33.2@5240,3315.94 ; C33.2@5227,3315.94 FPGA1.66@5298.74,3315.94 ; C33.2@5227,3315.94 C33.2@5240,3315.94 ; C33.2@5227,3315.94 C33.2@5240,3315.94 ; C33.2@5240,3315.94 FPGA1.66@5298.74,3315.94 ; C33.2@5240,3315.94 FPGA1.66@5298.74,3315.94 ; 5457.3,3032.7 5460,3030 C35.2@5460,2887.56 ; 5457.3,3032.7 FPGA1.81@5457.3,3078.74 ; 5457.3,3032.7 5457.3,3129.7 ; 5457.3,3032.7 FPGA1.81@5457.3,3078.74 ; 5457.3,3032.7 FPGA1.81@5457.3,3078.74 ; FPGA1.81@5457.3,3078.74 5457.3,3129.7 ; FPGA1.81@5457.3,3078.74 5457.3,3129.7 ; C35.2@5460,2887.56 C36.2@5520,2887.56 ; C35.2@5460,2887.56 C36.2@5520,2887.56 ; C35.2@5460,2887.56 C36.2@5520,2887.56
  Signal 1 w20: C42.2@6306.02,3301.8 v1(6430.9,3301.8) 6496.9,3301.8 6511.3,3287.4 VR3.3@6572.2,3287.4
+3.3V: C11.2 C15.2 C16.2 C21.2 C22.2 C23.2 C24.2 C25.2 C26.2 C28.2 C29.2 C30.2 C31.2 C34.2 C38.2 C40.2 C43.1 C44.2 FPGA1.11 FPGA1.22 FPGA1.26 FPGA1.45 FPGA1.55 FPGA1.67 FPGA1.68 FPGA1.79 FPGA1.92 FPGA1.96 P1.2 R12.1 U1.8 U2.3 U2.8 U2.19 U4.14 U4.19 U5.18 U5.19 U5.20 VR1.1 VR1.2 VR1.3 | length 5768.3
  Signal 1 w10: v1(4589.72,3204.84) U5.20@4687.8,3204.84 ; C25.2@4680,3145.59 4687.8,3153.39 U5.20@4687.8,3204.84 ; U5.18@4687.8,3256.02 U5.19@4687.8,3230.43 U5.20@4687.8,3204.84 ; R12.1@4825.59,4180 4909.6,4180 v1(4920.1,4169.5) 4945.72,4195.12 C21.2@5000,4195.12 5064.68,4195.12 5087,4172.8 5117.56,4172.8 C23.2@5120,4170.35 ; C26.2@4914.43,3117.04 4901.95,3117.04 4880,3138.99 4880,3154.74 4851.85,3182.89 4836.1,3182.89 4814.15,3204.84 U5.20@4687.8,3204.84 ; C43.1@5060.59,3755 v1(5135,3755) 5135,3665.12 5145.36,3654.76 5150.25,3654.76 5187.56,3617.44 5187.56,3557.44 5212.52,3532.48 FPGA1.55@5298.74,3532.48 ; C31.2@5180,3314.41 5180,3277.9 FPGA1.68@5297.41,3277.9 ; U2.8@5268.72,4144.07 U2.8@5271.72,4141.07 ; U2.8@5268.72,4144.08 5242.44,4170.35 ; FPGA1.67@5298.74,3296.26 FPGA1.68@5298.74,3279.23 ; FPGA1.68@5301.39,3276.57 v1(5447.23,3276.57) ; C34.2@5320,2885.59 5283,2848.59 5283,2778.5 5293.5,2768 v1(5330.4,2768) ; v1@5350,3792.8 v1@5350,3802.8 ; v1(5356.6,4376.5) 5408.94,4376.5 C24.2@5412.44,4380 ; U2.19@5379.69,3989.29 5379.69,3902.48 C22.2@5352.44,3875.24 ; U2.3@5379.69,4176.3 5379.69,4231.19 5412.44,4263.94 ; FPGA1.79@5417.83,3078.74 5417.83,3012.95 5320,2915.12 C34.2@5320,2887.56 ; FPGA1.45@5457.2,3674.06 5457.2,3735.59 5447.2,3735.59 5380,3802.8 ; v1@5669.9,2908.6 v1(5669.9,2917) 5669.9,2964.5 5673.74,2968.34 FPGA1.92@5673.74,3078.74 5673.74,3117.34 5686.52,3130.12 5752.48,3130.12 FPGA1.96@5752.48,3078.74 ; v1(5812.2,3338) 5839.1,3338 5841.47,3335.63 FPGA1.11@5891.26,3335.63 ; FPGA1.26@5831.22,3671.26 5831.22,3715.28 5840.94,3725 5877,3725 ; FPGA1.11@5891.26,3335 FPGA1.11@5891.26,3335.63 ; FPGA1.22@5891.26,3552.17 5999.73,3552.17 C28.2@6000,3552.44 ; v1(5921.5,2763.1) 5944.6,2740 C16.2@5984.88,2740 ; C15.2@5954.41,2660 5954.41,2679.91 5984.88,2710.38 C16.2@5984.88,2740 ; C44.2@5960,3354.41 5960,3337.36 5958.27,3335.63 FPGA1.11@5891.26,3335.63 ; C40.2@5972.44,3700 5968.44,3696 v1@5906,3696 ; v1(5976.4,2960.4) 6000.2,2960.4 6018.4,2978.6 U4.14@6063.1,2978.6 ; U4.19@6063.1,2850.2 6028.9,2850.2 6014.41,2835.71 6014.41,2833.01 5984.88,2803.48 C16.2@5984.88,2740 ; v1(6070,3550) v1@6067.56,3552.44 ; U1.8@6651.11,2588.19 6651.11,2553.64 6704.75,2500 6777.2,2500 ; v1@6791.6,2465.5 v1(6778.8,2465.5) ; C11.2@6800,2425.59 6778.8,2446.79 v1(6778.8,2465.5) ; C23.2@5120,4170.35 5242.44,4170.35 ; C23.2@5120,4170.35 5242.44,4170.35 ; C23.2@5120,4170.35 5242.44,4170.35 ; v1@5137.56,3752.44 C30.2@5200,3752.44 ; v1@5137.56,3752.44 C30.2@5200,3752.44 ; v1@5137.56,3752.44 C30.2@5200,3752.44 ; FPGA1.68@5297.41,3277.9 FPGA1.68@5298.74,3279.23 ; FPGA1.68@5297.41,3277.9 FPGA1.68@5298.74,3279.23 ; FPGA1.68@5297.41,3277.9 FPGA1.68@5298.74,3279.23 ; C34.2@5320,2887.56 C29.2@5380,2887.56 ; C34.2@5320,2887.56 C29.2@5380,2887.56 ; C34.2@5320,2887.56 C29.2@5380,2887.56 ; v1@5350,3802.8 v1@5350,3807.8 ; v1@5350,3802.8 5380,3802.8 ; v1@5350,3802.8 5380,3802.8 ; v1@5350,3802.8 C22.2@5350,3860.35 ; v1@5350,3802.8 C22.2@5350,3860.35 ; v1@5350,3807.8 C22.2@5350,3860.35 ; v1@5350,3807.8 C22.2@5350,3860.35 ; v1@5350,3807.8 C22.2@5350,3860.35 ; C22.2@5350,3860.35 C22.2@5352.44,3862.8 ; C22.2@5352.44,3862.8 C22.2@5352.44,3875.24 ; C22.2@5352.44,3862.8 C22.2@5352.44,3875.24 ; C22.2@5352.44,3862.8 C22.2@5352.44,3875.24 ; 5412.44,4263.94 C24.2@5412.44,4380 ; 5412.44,4263.94 C24.2@5412.44,4380 ; 5412.44,4263.94 C24.2@5412.44,4380 ; 5877,3725 v1@5899.2,3702.8 ; 5877,3725 v1@5899.2,3702.8 ; 5877,3725 v1@5906,3696 ; v1@5899.2,3702.8 v1@5906,3696 ; v1@5899.2,3702.8 v1@5906,3696 ; v1@5899.2,3702.8 v1@5906,3696 ; C28.2@6000,3552.44 v1@6067.56,3552.44 ; C28.2@6000,3552.44 v1@6067.56,3552.44 ; C28.2@6000,3552.44 v1@6067.56,3552.44 ; v1(6778.8,2465.5) 6778.8,2498.4 v1(6778.8,2465.5)
  other v1: 6661.9,1750.9 6661.9,1836.3 6730.4,1836.3 6657.9,1904.4 5899.8,3703.4 5340,3807.8
+5V: C1.1 C3.1 C5.2 C6.2 C7.2 C8.2 C13.2 C14.2 C37.2 C41.2 D1.1 P2.A4 R6.1 R7.2 R13.1 U3.K1 U3.K2 U3.M13 U3.M14 U3.N4 U3.P5 U4.5 U4.6 U4.13 VR1.6 VR1.7 VR1.8 VR3.1 | length 2006.5
  Signal 1 w10: C5.2@5320,2364.88 C6.2@5220,2364.88 5211.7,2356.58 v1(5211.7,2288.1) 5217.6,2282.2 U3.M14@5474.1,2282.2 U3.M13@5513.5,2282.2 ; C8.2@5865.12,2650 C7.2@5865.12,2550 5845,2529.88 v1(5845,2455) 5845,2377.5 U3.P5@5828.4,2360.9 U3.N4@5867.8,2321.5 ; v1(5935.5,3006.7) 5938.4,3003.8 U4.13@6063.1,3003.8 ; U3.K2@5946.5,2203.4 U3.K1@5985.9,2203.4 5994.3,2195 6139.88,2195 ; v1(6100,2195) 6139.88,2195 ; C3.1@6194.88,2150 6149.88,2195 6139.88,2195 ; C1.1@6194.88,2250 6139.88,2195 ; R7.2@6197.4,2660 6257.4,2660 v1(6269.8,2647.6) 6297.99,2647.6 R13.1@6320,2625.59 ; U4.6@6296.9,2952.6 U4.5@6296.9,2927.4 6354.3,2927.4 6372.49,2945.59 C13.2@6400,2945.59 6429.31,2974.9 6478.9,2974.9 6480,2976 C14.2@6480,3015.12 6477.2,3017.92 v1(6477.2,3091.9) ; v1(6479.08,1744.63) 6483,1748.55 D1.1@6483,1831.12 ; R6.1@6636.7,3006.22 6708.68,3006.22 v1(6710.5,3004.4)
  other v1: 6672.6,2057.3 6672.6,2137.2 6653.4,2314.9 6564.9,3404.7
+210V: C2.1 C4.1 D1.2 P2.A2 U3.H1 U3.H2 | length 3922.9
  Signal 1 w10: U3.H2@5946.5,2124.7 6060.3,2124.7 6120,2065 6230.12,2065 6240,2055.12 C2.1@6340,2055.12 C2.1@6370.12,2025 ; D1.2@6483,2018 D1.2@6483,2008.28 ; C2.1@6370.12,2025 6483,2025 6490,2025 C2.1@6370.12,2025 ; D1.2@6483,2008.28 v1(6482.9,1929.2) D1.2@6483,2008.28
  Signal 4 w10: P2.A2@6410,1248.66 6484.33,1174.33 6560.07,1174.33 6570.25,1174.33 6733.3,1337.38 6733.3,1546.66 6715.3,1564.65 6668.06,1564.65 6588.68,1644.03 6588.68,1651.9 6588.68,1863.37 6524.48,1927.57 v1@6483,1927.57 ; v1(6482.9,1929.2) 6615.7,2062 6615.7,2203 6591.6,2227.1 6591.6,2353.1 6603.1,2364.6 6615.4,2364.6 6652.9,2402.1 C4.1@6652.9,3714.47
-5V: C9.2 C10.2 D2.1 P2.A3 R8.1 U3.L1 U3.L2 | length 3317.1
  Signal 1 w10: U3.L2@5946.5,2242.8 6087.68,2242.8 C9.2@6194.88,2350 6194.88,2550.12 6191.2,2553.8 R8.1@6190,2555 ; v1(6096,2351.6) C9.2@6204.5,2351.6 ; P2.A3@6310,1248.66 6361.94,1196.72 6575.13,1196.72 6630.62,1252.21 6762.81,1252.21 v1(6879.53,1368.93) ; v1(6394.02,2361.32) 6414.39,2361.32 D2.1@6490,2436.93 ; v1(6681.55,1505.04) 6700.68,1485.91 v1(6810.91,1485.91)
  Signal 4 w10: v1(6394.02,2361.32) 6384.3,2351.6 v1(6096,2351.6) 6096,2244.8 6062,2210.8 6062,2179.2 6096,2145.2 6096,1719.9 6195.39,1620.51 6489.59,1620.51 6605.06,1505.04 v1(6681.55,1505.04) ; v1(6810.91,1485.91) 6879.53,1417.3 v1(6879.53,1368.93)
AD5535/AGND: C1.2 C2.2 C3.2 C4.2 C5.1 C6.1 C9.1 C10.1 C12.1 C13.1 C14.1 C15.1 C16.1 D2.2 P2.A5 R1.1 R9.2 U3.H4 U3.H5 U3.H6 U3.H7 U3.H8 U3.H9 U3.H10 U3.H11 U3.J3 U3.J4 U3.J5 U3.J6 U3.J7 U3.J8 U3.J9 U3.J10 U3.J11 U3.J12 U3.K3 U3.K4 U3.K5 U3.K6 U3.K7 U3.K8 U3.K9 U3.K10 U3.K11 U3.K12 U3.K13 U3.K14 U3.L3 U3.L4 U3.L5 U3.L6 U3.L7 U3.L8 U3.L9 U3.L10 U3.L11 U3.L12 U3.L13 U3.L14 U3.M1 U3.M2 U3.M3 U3.M4 U3.M5 U3.M6 U3.M7 U3.M8 U3.M9 U3.M10 U3.M11 U3.M12 U3.N1 U3.N2 U3.N5 U3.N6 U3.N7 U3.N8 U3.N9 U3.N10 U3.N11 U3.N12 U3.N13 U3.N14 U3.P3 U3.P11 U3.P12 U3.P13 U4.4 U4.8 U4.17 U4.20 | length 19709.8
  Signal 1 w10: v1@4980,1928.8 R9.2@4980,2002.6 ; v1(5142.6,2473.4) 5144.32,2475.12 C6.1@5220,2475.12 C5.1@5320,2475.12 ; v1(5412.1,2339.2) 5434.7,2339.2 5452.4,2321.5 ; U3.N14@5474.1,2321.5 5452.4,2321.5 ; U3.K13@5513.5,2203.4 U3.K14@5474.1,2203.4 ; U3.L13@5513.5,2242.8 U3.L12@5552.8,2242.8 ; U3.H6@5789.1,2124.7 U3.H11@5592.2,2124.7 ; U3.K6@5789.1,2203.4 U3.K6@5790,2203.4 ; U3.L6@5789.1,2242.8 U3.L14@5474.1,2242.8 ; U3.M6@5789.1,2282.2 U3.M12@5552.8,2282.2 ; U3.H5@5828.4,2124.7 U3.H11@5592.2,2124.7 ; U3.J5@5828.4,2164.1 U3.J12@5552.8,2164.1 ; U3.K5@5828.4,2203.4 U3.K14@5474.1,2203.4 ; U3.L5@5828.4,2242.8 U3.L14@5474.1,2242.8 ; U3.M5@5828.4,2282.2 U3.M12@5552.8,2282.2 ; U3.N5@5828.4,2321.5 U3.N6@5789.1,2321.5 ; U3.P3@5907.2,2360.9 5907.2,2387.2 v1(5975,2455) 5975,2564.5 5973.91,2565.59 R1.1@5940,2565.59 ; v1(5920.1,2858.6) 5931.6,2858.6 5955.3,2882.3 5999.2,2882.3 6018.3,2901.4 U4.17@6063.1,2901.4 ; U3.M1@5985.9,2282.2 U3.N1@5985.9,2321.5 U3.N2@5946.5,2321.5 U3.M2@5946.5,2282.2 U3.M3@5907.2,2282.2 ; C15.1@6005.59,2660 6034.6,2660 6095.12,2720.52 C16.1@6095.12,2740 ; U4.20@6065.59,2822.51 U4.20@6063.1,2825 6063.1,2805.7 6095.12,2773.68 C16.1@6095.12,2740 ; v1(6164.3,2727.7) C16.1@6107.42,2727.7 ; v1(6280.1,3876.3) 6442.1,3714.3 C4.2@6450.8,3714.3 ; U4.8@6296.9,3003.8 6325.81,3003.8 6336.98,3014.98 6336.98,3050.86 6351.75,3065.62 v1(6351.75,3114.3) 6388.71,3114.3 C12.1@6400,3125.59 ; C1.2@6305.12,2250 C3.2@6305.12,2150 ; C10.1@6305.12,2450 C9.1@6305.12,2350 C3.2@6305.12,2150 ; C2.2@6340,1944.88 v1(6341.24,1865.97) ; C14.1@6480,2894.41 6480,2870.2 6500.8,2849.4 6500.8,2786.9 v1(6484.6,2770.7) ; C14.1@6480,2904.88 C14.1@6476.52,2901.4 ; D2.2@6490,2303.07 6490,2229.8 v1(6563.6,2156.2) 6413.6,2156.2 6407.4,2150 C3.2@6305.12,2150 ; 5452.4,2321.5 U3.N13@5513.5,2321.5 U3.N13@5515,2321.5 ; U3.K14@5474.1,2203.4 U3.K4@5867.8,2203.4 ; U3.K14@5474.1,2203.4 U3.K5@5830,2203.4 ; U3.K14@5474.1,2203.4 U3.K6@5790,2203.4 ; U3.K14@5474.1,2203.4 U3.K7@5749.7,2203.4 U3.H7@5749.7,2124.7 ; U3.K14@5474.1,2203.4 U3.K8@5710.3,2203.4 U3.H8@5710.3,2124.7 ; U3.K14@5474.1,2203.4 U3.K9@5670.9,2203.4 U3.H9@5670.9,2124.7 ; U3.K14@5474.1,2203.4 U3.K10@5631.6,2203.4 U3.H10@5631.6,2124.7 ; U3.K14@5474.1,2203.4 U3.K11@5592.2,2203.4 ; U3.L14@5474.1,2242.8 U3.L4@5867.8,2242.8 ; U3.L14@5474.1,2242.8 U3.L5@5830,2242.8 ; U3.L14@5474.1,2242.8 U3.L6@5790,2242.8 ; U3.L14@5474.1,2242.8 U3.L7@5749.7,2242.8 U3.H7@5749.7,2124.7 ; U3.L14@5474.1,2242.8 U3.L8@5710.3,2242.8 U3.H8@5710.3,2124.7 ; U3.L14@5474.1,2242.8 U3.L9@5670.9,2242.8 U3.H9@5670.9,2124.7 ; U3.L14@5474.1,2242.8 U3.L10@5631.6,2242.8 U3.H10@5631.6,2124.7 ; U3.L14@5474.1,2242.8 U3.L11@5592.2,2242.8 U3.H11@5592.2,2124.7 ; U3.L14@5474.1,2242.8 U3.L12@5552.8,2242.8 ; U3.N13@5515,2321.5 U3.P13@5515,2359.4 ; U3.N13@5515,2321.5 U3.P13@5515,2359.4 ; U3.N13@5515,2321.5 U3.P13@5515,2359.4 ; U3.P13@5515,2359.4 U3.P13@5516.5,2360.9 ; U3.P13@5515,2359.4 U3.P13@5516.5,2360.9 ; U3.P13@5515,2359.4 U3.P13@5516.5,2360.9 ; U3.P13@5516.5,2360.9 U3.P12@5552.8,2360.9 U3.P11@5592.2,2360.9 U3.N11@5592.2,2321.5 ; U3.J12@5552.8,2164.1 U3.J4@5867.8,2164.1 ; U3.J12@5552.8,2164.1 U3.J5@5830,2164.1 ; U3.J12@5552.8,2164.1 U3.J6@5790,2164.1 ; U3.J12@5552.8,2164.1 U3.J6@5789.1,2164.1 U3.J7@5749.7,2164.1 U3.H7@5749.7,2124.7 ; U3.J12@5552.8,2164.1 U3.J8@5710.3,2164.1 U3.H8@5710.3,2124.7 ; U3.J12@5552.8,2164.1 U3.K12@5552.8,2203.4 ; U3.J12@5552.8,2164.1 U3.J9@5670.9,2164.1 U3.H9@5670.9,2124.7 ; U3.J12@5552.8,2164.1 U3.J10@5631.6,2164.1 U3.H10@5631.6,2124.7 ; U3.J12@5552.8,2164.1 U3.J11@5592.2,2164.1 U3.H11@5592.2,2124.7 ; U3.K12@5552.8,2203.4 U3.L12@5552.8,2242.8 ; U3.K12@5552.8,2203.4 U3.K11@5592.2,2203.4 ; U3.M12@5552.8,2282.2 U3.N12@5552.8,2321.5 ; U3.M12@5552.8,2282.2 U3.M4@5867.8,2282.2 ; U3.M12@5552.8,2282.2 U3.M5@5830,2282.2 ; U3.M12@5552.8,2282.2 U3.M6@5790,2282.2 ; U3.M12@5552.8,2282.2 U3.M7@5749.7,2282.2 ; U3.M12@5552.8,2282.2 U3.M8@5710.3,2282.2 ; U3.M12@5552.8,2282.2 U3.M9@5670.9,2282.2 ; U3.M12@5552.8,2282.2 U3.M11@5592.2,2282.2 U3.H11@5592.2,2124.7 ; U3.N12@5552.8,2321.5 U3.N6@5789.1,2321.5 ; U3.N12@5552.8,2321.5 U3.N8@5710.3,2321.5 U3.M8@5710.3,2282.2 ; U3.N12@5552.8,2321.5 U3.N9@5670.9,2321.5 ; U3.N12@5552.8,2321.5 U3.N11@5592.2,2321.5 ; U3.H11@5592.2,2124.7 U3.H5@5830,2124.7 ; U3.H11@5592.2,2124.7 U3.N11@5592.2,2321.5 ; U3.H11@5592.2,2124.7 U3.H6@5790,2124.7 ; U3.H11@5592.2,2124.7 U3.H7@5749.7,2124.7 ; U3.H11@5592.2,2124.7 U3.H8@5710.3,2124.7 ; U3.H11@5592.2,2124.7 U3.H9@5670.9,2124.7 ; U3.H11@5592.2,2124.7 U3.K11@5592.2,2203.4 ; U3.H11@5592.2,2124.7 U3.H10@5631.6,2124.7 ; U3.H10@5631.6,2124.7 U3.M10@5631.6,2282.2 ; U3.M10@5631.6,2282.2 U3.N10@5631.6,2321.5 U3.N9@5670.9,2321.5 ; U3.M10@5631.6,2282.2 U3.M9@5670.9,2282.2 ; U3.H9@5670.9,2124.7 U3.M9@5670.9,2282.2 ; U3.M9@5670.9,2282.2 U3.N9@5670.9,2321.5 ; U3.H8@5710.3,2124.7 U3.M8@5710.3,2282.2 ; U3.H7@5749.7,2124.7 U3.M7@5749.7,2282.2 ; U3.M7@5749.7,2282.2 U3.N7@5749.7,2321.5 U3.N6@5789.1,2321.5 ; U3.N6@5789.1,2321.5 U3.N6@5790,2320.6 ; U3.H6@5790,2124.7 U3.J6@5790,2164.1 ; U3.H6@5790,2124.7 U3.N6@5790,2320.6 ; U3.H6@5790,2124.7 U3.M6@5790,2282.2 ; U3.H6@5790,2124.7 U3.M6@5790,2282.2 ; U3.H6@5790,2124.7 U3.L6@5790,2242.8 ; U3.H6@5790,2124.7 U3.L6@5790,2242.8 ; U3.H6@5790,2124.7 U3.K6@5790,2203.4 ; U3.H6@5790,2124.7 U3.K6@5790,2203.4 ; U3.H6@5790,2124.7 U3.J6@5790,2164.1 ; U3.H6@5790,2124.7 U3.J6@5790,2164.1 ; U3.J6@5790,2164.1 U3.K6@5790,2203.4 ; U3.K6@5790,2203.4 U3.L6@5790,2242.8 ; U3.L6@5790,2242.8 U3.M6@5790,2282.2 ; U3.M6@5790,2282.2 U3.N6@5790,2320.6 ; U3.M6@5790,2282.2 U3.N6@5790,2320.6 ; U3.H5@5830,2124.7 U3.J5@5830,2164.1 ; U3.H5@5830,2124.7 U3.H4@5867.8,2124.7 ; U3.H5@5830,2124.7 U3.M5@5830,2282.2 ; U3.H5@5830,2124.7 U3.L5@5830,2242.8 ; U3.H5@5830,2124.7 U3.L5@5830,2242.8 ; U3.H5@5830,2124.7 U3.K5@5830,2203.4 ; U3.H5@5830,2124.7 U3.K5@5830,2203.4 ; U3.H5@5830,2124.7 U3.J5@5830,2164.1 ; U3.H5@5830,2124.7 U3.J5@5830,2164.1 ; U3.J5@5830,2164.1 U3.K5@5830,2203.4 ; U3.K5@5830,2203.4 U3.L5@5830,2242.8 ; U3.L5@5830,2242.8 U3.M5@5830,2282.2 ; U3.L5@5830,2242.8 U3.M5@5830,2282.2 ; U3.H4@5867.8,2124.7 U3.L4@5867.8,2242.8 ; U3.H4@5867.8,2124.7 U3.K4@5867.8,2203.4 ; U3.H4@5867.8,2124.7 U3.J4@5867.8,2164.1 ; U3.J4@5867.8,2164.1 U3.J3@5907.2,2164.1 ; U3.K4@5867.8,2203.4 U3.K3@5907.2,2203.4 U3.J3@5907.2,2164.1 ; U3.L4@5867.8,2242.8 U3.M4@5867.8,2282.2 ; U3.L4@5867.8,2242.8 U3.L3@5907.2,2242.8 ; U3.M4@5867.8,2282.2 U3.M3@5907.2,2282.2 ; U3.J3@5907.2,2164.1 U3.L3@5907.2,2242.8 ; U3.L3@5907.2,2242.8 U3.M3@5907.2,2282.2 ; C16.1@6095.12,2740 C16.1@6107.42,2727.7 ; C16.1@6095.12,2740 C16.1@6107.42,2727.7 ; U4.4@6296.9,2901.4 C13.1@6400,2901.4 ; U4.4@6296.9,2901.4 C14.1@6476.52,2901.4 ; U4.4@6296.9,2901.4 C13.1@6400,2901.4 ; U4.4@6296.9,2901.4 C13.1@6400,2901.4 ; C13.1@6400,2901.4 C14.1@6476.52,2901.4 ; C13.1@6400,2901.4 C14.1@6476.52,2901.4
  other v1: 4983.38,1925.43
